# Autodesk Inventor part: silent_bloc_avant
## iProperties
Shininess: 64.0
Length Units: 11269
Angle Units: 11279
Time Units: 11290
Mass Units: 11283
Length Display Precision: 3
Angle Display Precision: 2
Compacted: True
Part Number: silent_bloc_avant
Document SubType Name: Modeling
Created: 2004-05
Material: Par défaut
Designer: David
Density: 0.0
Volumn: 0.0
Area: 0.0
PropertySet Name: Model Information
Control State: 0
Master: False
Checked Out: False
Author: David
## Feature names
1. Extrusion1
2. Extrusion5
3. Extrusion6
